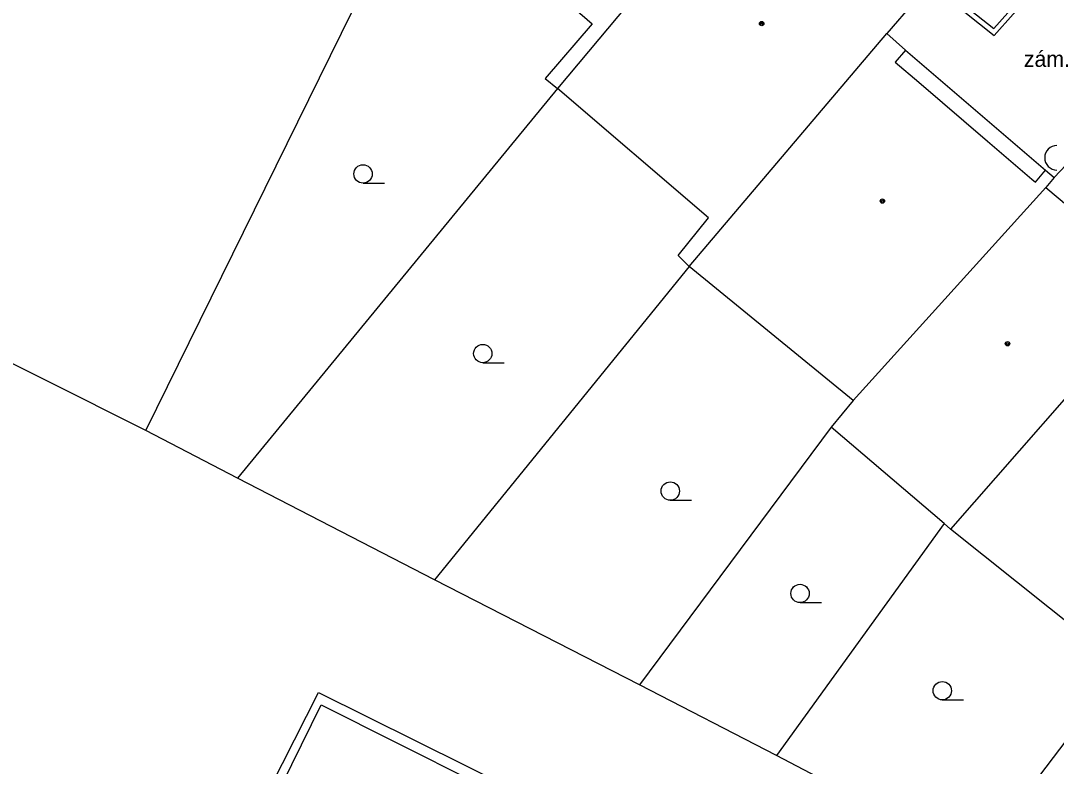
# Model space of a CAD drawing. Extents: x -600309 to -598967, y -1161267 to -1160292.
# Drawn here: x -600023.62 to -599981.24, y -1160711.09 to -1160680.58 of the extents above; entities that cross this region are included whole.
import ezdxf

# ---------------------------------------------------------------- set-up
doc = ezdxf.new("R2010")
doc.units = 0
for name, color, linetype in [('Level 11', 7, 'Continuous'), ('Level 22', 7, 'Continuous'), ('Level 36', 7, 'Continuous'), ('Level 39', 7, 'Continuous'), ('Level 40', 7, 'Continuous'), ('Level 5', 7, 'Continuous'), ('Level 51', 7, 'Continuous'), ('Level 54', 7, 'Continuous'), ('Level 8', 7, 'Continuous')]:
    doc.layers.add(name, color=color, linetype=linetype)

msp = doc.modelspace()

# ---------------------------------------------------------------- linework, layer by layer
at = {"layer": 'Level 11'}
for points in [[(-599985.82, -1160678.29), (-599985.76, -1160679.4099), (-599985.65, -1160679.68), (-599983.78, -1160681.18), (-599980.68, -1160677.68)], [(-599985.63, -1160678.05), (-599985.56, -1160679.37), (-599985.48, -1160679.56), (-599983.8, -1160680.9), (-599980.83, -1160677.55)], [(-599980.33, -1160685.95), (-599981.33, -1160687)]]:
    msp.add_lwpolyline(points, dxfattribs=at)
at = {"layer": 'Level 22'}
msp.add_arc((-599981.2199, -1160686.19), 0.5, 90, 270, dxfattribs=at)
at = {"layer": 'Level 36'}
for p, q in [((-600009.61, -1160687.225), (-600008.735, -1160687.225)), ((-600004.71, -1160694.575), (-600003.835, -1160694.575)), ((-599997.04, -1160700.205), (-599996.165, -1160700.205)), ((-599991.73, -1160704.395), (-599990.855, -1160704.395)), ((-599985.9099, -1160708.375), (-599985.0349, -1160708.375))]:
    msp.add_line(p, q, dxfattribs=at)
for centre in [(-600009.6101, -1160686.8499), (-600004.7101, -1160694.1999), (-599997.0401, -1160699.8299), (-599991.7301, -1160704.0199), (-599985.91, -1160707.9999)]:
    msp.add_circle(centre, 0.375, dxfattribs=at)
at = {"layer": 'Level 39'}
for centre, radius in [((-599993.3, -1160680.7), 0.09), ((-599993.3, -1160680.7), 0.0398), ((-599988.36, -1160687.96), 0.09), ((-599988.36, -1160687.96), 0.0398), ((-599983.24, -1160693.8), 0.09), ((-599983.24, -1160693.8), 0.0398)]:
    msp.add_circle(centre, radius, dxfattribs=at)
at = {"layer": 'Level 5'}
for points in [[(-599994.18, -1160674.42), (-600001.6599, -1160683.35)], [(-600005.09, -1160676.49), (-600000.23, -1160680.71)], [(-599987.05, -1160679.8), (-599988.18, -1160681.11)], [(-600000.23, -1160680.71), (-600002.1599, -1160682.94)], [(-599996.26, -1160690.64), (-599988.18, -1160681.11)], [(-599988.18, -1160681.11), (-599987.42, -1160681.78)], [(-599987.42, -1160681.78), (-599987.84, -1160682.27)], [(-599987.42, -1160681.78), (-599981.68, -1160686.7)], [(-599987.84, -1160682.27), (-599986.87, -1160683.1)], [(-600002.1599, -1160682.94), (-600001.6599, -1160683.35)], [(-599986.87, -1160683.1), (-599984.06, -1160685.51)], [(-599995.4699, -1160688.65), (-600001.6599, -1160683.35)], [(-599984.06, -1160685.51), (-599982.25, -1160687.06)], [(-599982.1, -1160687.19), (-599981.68, -1160686.7)], [(-599981.68, -1160686.7), (-599981.33, -1160687)], [(-599982.25, -1160687.06), (-599982.1, -1160687.19)], [(-599981.33, -1160687), (-599981.67, -1160687.4)], [(-599981.67, -1160687.4), (-599989.56, -1160696.12)], [(-599981.67, -1160687.4), (-599980.74, -1160688.19)], [(-599996.7199, -1160690.19), (-599995.4699, -1160688.65)], [(-599996.26, -1160690.64), (-599996.7199, -1160690.19)], [(-599989.56, -1160696.12), (-599996.26, -1160690.64)], [(-599978.11, -1160692.88), (-599985.58, -1160701.39)], [(-599989.56, -1160696.12), (-599990.46, -1160697.2199)], [(-599985.83, -1160701.1599), (-599990.46, -1160697.2199)], [(-599985.58, -1160701.39), (-599985.83, -1160701.1599)], [(-599978.82, -1160706.78), (-599985.58, -1160701.39)]]:
    msp.add_lwpolyline(points, dxfattribs=at)
at = {"layer": 'Level 51'}
for points in [[(-600018.5, -1160697.35), (-600003.38, -1160666.65)], [(-600001.6599, -1160683.35), (-600014.75, -1160699.3)], [(-599996.26, -1160690.64), (-600006.69, -1160703.46)], [(-600018.5, -1160697.35), (-600030.78, -1160691.2)], [(-599990.46, -1160697.2199), (-599998.3, -1160707.76)], [(-600014.75, -1160699.3), (-600018.5, -1160697.35)], [(-600006.69, -1160703.46), (-600014.75, -1160699.3)], [(-599985.83, -1160701.1599), (-599992.69, -1160710.65)], [(-599998.3, -1160707.76), (-600006.69, -1160703.46)], [(-599992.69, -1160710.65), (-599998.3, -1160707.76)], [(-599979.96, -1160708.86), (-599984.55, -1160714.92)], [(-599984.55, -1160714.92), (-599992.69, -1160710.65)]]:
    msp.add_lwpolyline(points, dxfattribs=at)
at = {"layer": 'Level 54'}
for points in [[(-600013.89, -1160712.9099), (-600011.43, -1160708.07)], [(-600011.43, -1160708.07), (-600001.4099, -1160713.05)], [(-600013.33, -1160712.6599), (-600011.32, -1160708.58)], [(-600011.32, -1160708.58), (-600001.93, -1160713.3)]]:
    msp.add_lwpolyline(points, dxfattribs=at)
at = {"layer": 'Level 8'}
msp.add_lwpolyline([(-599984.06, -1160685.51), (-599982.25, -1160687.06)], dxfattribs=at)

# ---------------------------------------------------------------- texts
at = {"layer": 'Level 40'}
msp.add_text('zám.', height=0.65, dxfattribs=at).set_placement((-599982.57, -1160682.4699))

doc.saveas('drawing.dxf')
